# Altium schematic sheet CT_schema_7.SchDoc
size 479 x 328 mm
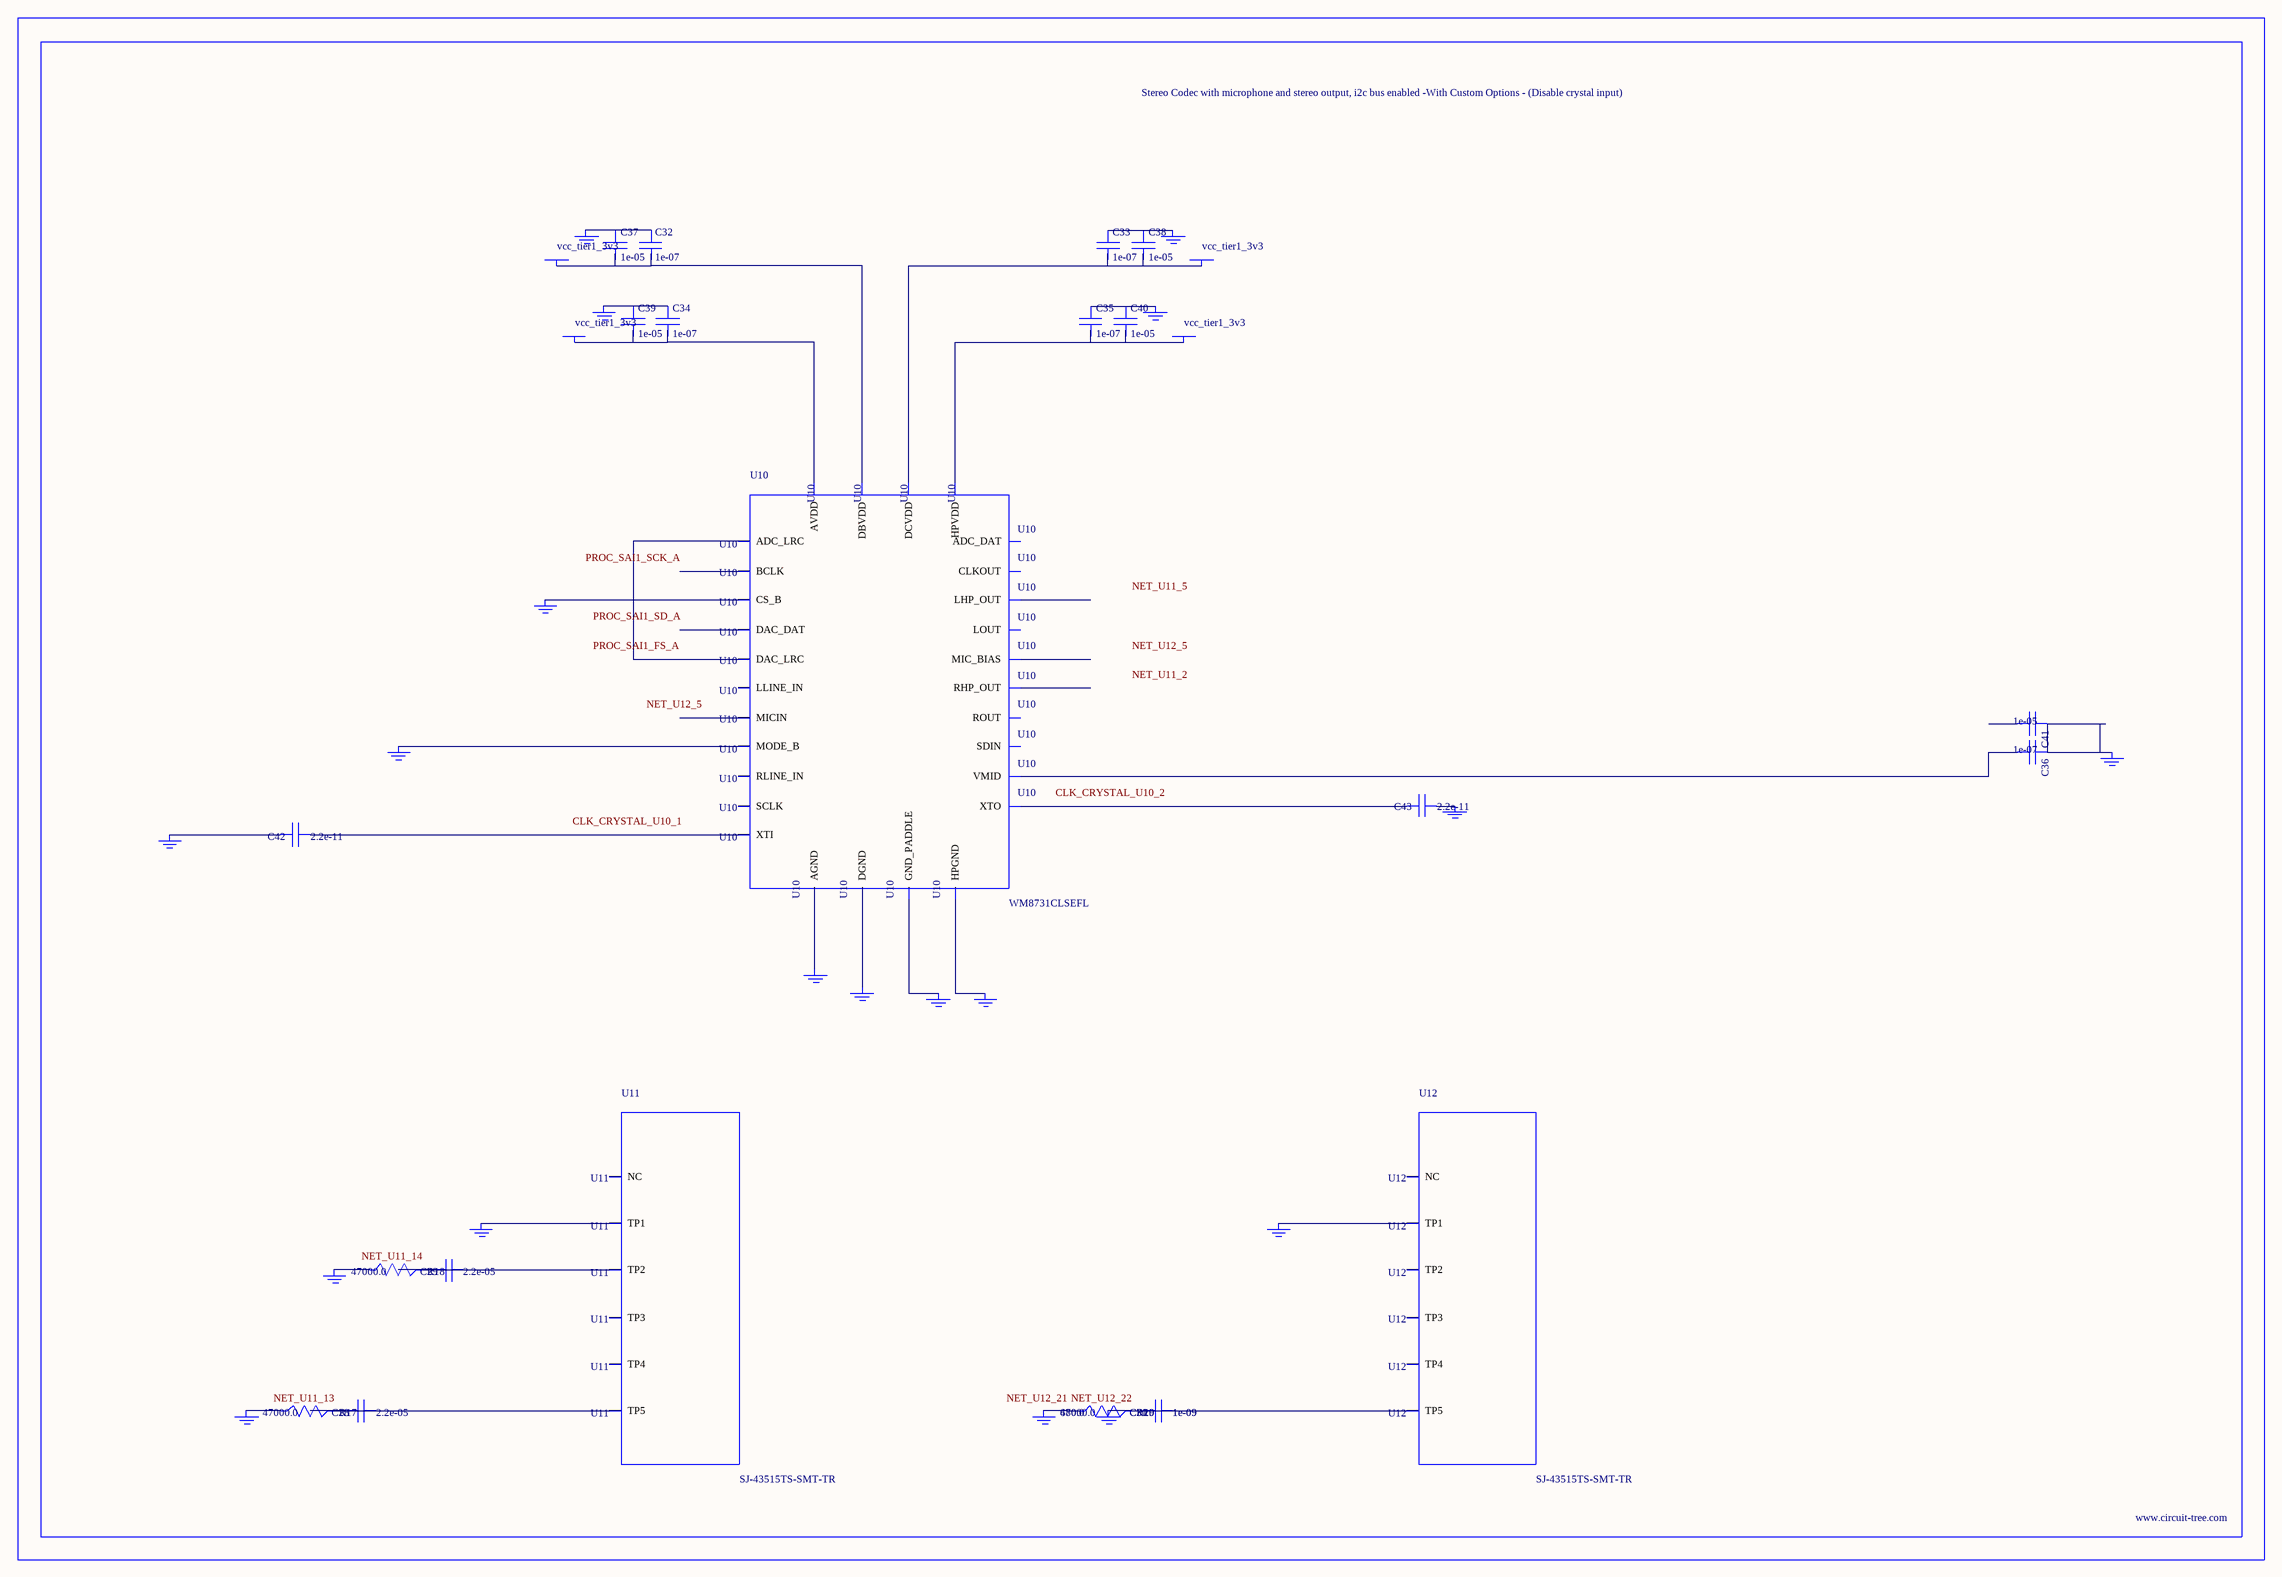
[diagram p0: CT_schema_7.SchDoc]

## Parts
BORDER6  (no value)
C28  2.2e-05  [C1210]
C29  2.2e-05  [C1210]
C30  1e-09  [C0402]
C31  1e-09  [C0402]
C32  1e-07  [C0402]
C33  1e-07  [C0402]
C34  1e-07  [C0402]
C35  1e-07  [C0402]
C36  1e-07  [C0402]
C37  1e-05  [C0805]
C38  1e-05  [C0805]
C39  1e-05  [C0805]
C40  1e-05  [C0805]
C41  1e-05  [C0805]
C42  2.2e-11  [C0402]
C43  2.2e-11  [C0402]
GND_INSTANCE_6_0  (no value)
GND_INSTANCE_6_1  (no value)
GND_INSTANCE_6_2  (no value)
GND_INSTANCE_6_3  (no value)
GND_INSTANCE_6_4  (no value)
GND_INSTANCE_6_5  (no value)
GND_INSTANCE_6_6  (no value)
GND_INSTANCE_6_7  (no value)
GND_INSTANCE_6_8  (no value)
GND_INSTANCE_6_9  (no value)
GND_INSTANCE_6_10  (no value)
GND_INSTANCE_6_11  (no value)
GND_INSTANCE_6_12  (no value)
GND_INSTANCE_6_13  (no value)
GND_INSTANCE_6_14  (no value)
GND_INSTANCE_6_15  (no value)
GND_INSTANCE_6_16  (no value)
GND_INSTANCE_6_17  (no value)
GND_INSTANCE_6_18  (no value)
POWER_INSTANCE_6_0  vcc_tier1_3v3
POWER_INSTANCE_6_1  vcc_tier1_3v3
POWER_INSTANCE_6_2  vcc_tier1_3v3
POWER_INSTANCE_6_3  vcc_tier1_3v3
R17  47000.0  [R0603]
R18  47000.0  [R0603]
R19  47000.0  [R0603]
R20  680.0  [R0603]
U10  WM8731CLSEFL  [QFN-28]
U11  SJ-43515TS-SMT-TR  [SJ-43515TS-SMT-TR]
U12  SJ-43515TS-SMT-TR  [SJ-43515TS-SMT-TR]

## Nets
NetC28_1: C28.1 C28.2 R17.2 U11.5(TP5)
NetC29_1: C29.1 C29.2 R18.2 U11.2(TP2)
NetC30_1: C30.1 C30.2 C31.1 C31.2 GND_INSTANCE_6_18.0(GND) R19.2 R20.2 U12.5(TP5)
NetC32_1: C32.1 C37.1 GND_INSTANCE_6_3.0(GND)
NetC32_2: C32.2 C37.2 POWER_INSTANCE_6_1.0(PWR) U10.5(DBVDD)
NetC33_1: C33.1 C38.1 GND_INSTANCE_6_2.0(GND)
NetC33_2: C33.2 C38.2 POWER_INSTANCE_6_0.0(PWR) U10.3(DCVDD)
NetC34_1: C34.1 C39.1 GND_INSTANCE_6_6.0(GND)
NetC34_2: C34.2 C39.2 POWER_INSTANCE_6_3.0(PWR) U10.18(AVDD)
NetC35_1: C35.1 C40.1 GND_INSTANCE_6_4.0(GND)
NetC35_2: C35.2 C40.2 POWER_INSTANCE_6_2.0(PWR) U10.12(HPVDD)
NetC36_1: C36.1 C41.1 GND_INSTANCE_6_7.0(GND)
NetC36_2: C36.2 U10.20(VMID)
NetC42_1: C42.1 U10.1(XTI)
NetC42_2: C42.2 GND_INSTANCE_6_0.0(GND)
NetC43_1: C43.1 GND_INSTANCE_6_1.0(GND)
NetC43_2: C43.2 U10.2(XTO)
NetGND_INSTANCE_6_5_0: GND_INSTANCE_6_5.0(GND) U10.15(HPGND)
NetGND_INSTANCE_6_8_0: GND_INSTANCE_6_8.0(GND) U10.25(MODE_B)
NetGND_INSTANCE_6_9_0: GND_INSTANCE_6_9.0(GND) U10.26(CS_B)
NetGND_INSTANCE_6_10_0: GND_INSTANCE_6_10.0(GND) U10.29(GND_PADDLE)
NetGND_INSTANCE_6_11_0: GND_INSTANCE_6_11.0(GND) U10.4(DGND)
NetGND_INSTANCE_6_12_0: GND_INSTANCE_6_12.0(GND) U10.19(AGND)
NetGND_INSTANCE_6_13_0: GND_INSTANCE_6_13.0(GND) U11.1(TP1)
NetGND_INSTANCE_6_14_0: GND_INSTANCE_6_14.0(GND) R18.1
NetGND_INSTANCE_6_15_0: GND_INSTANCE_6_15.0(GND) R17.1
NetGND_INSTANCE_6_16_0: GND_INSTANCE_6_16.0(GND) U12.1(TP1)
NetGND_INSTANCE_6_17_0: GND_INSTANCE_6_17.0(GND) R19.1 R20.1
NetU10_9: U10.9(DAC_LRC) U10.11(ADC_LRC)

Not connected (* = marked no-connect by the designer): C41 2; U10 6(CLKOUT) 7(BCLK) 8(DAC_DAT) 10(ADC_DAT) 13(LHP_OUT) 14(RHP_OUT) 16(LOUT) 17(ROUT) 21(MIC_BIAS) 22(MICIN) 23(RLINE_IN) 24(LLINE_IN) 27(SDIN) 28(SCLK); U11 3(TP3) 4(TP4) 6(NC); U12 2(TP2) 3(TP3) 4(TP4) 6(NC)

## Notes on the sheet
- Labels drawn without touching a wire or pin: CLK_CRYSTAL_U10_1, CLK_CRYSTAL_U10_2, NET_U11_2, NET_U11_5, NET_U11_13, NET_U11_14, NET_U12_5, NET_U12_21, NET_U12_22, PROC_SAI1_FS_A, PROC_SAI1_SCK_A, PROC_SAI1_SD_A

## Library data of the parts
BORDER6 = BORDER_PAGE6
C28 C29 = C1210C224K5RACTU
C30 C31 = C0402C102K3RAC
C32-C36 = C0402C104K3RACTU
C37-C41 = C0805C106K8RACTU
C42 C43 = C0402C220K3RAC
GND_INSTANCE_6_0-GND_INSTANCE_6_18 = GND
POWER_INSTANCE_6_0-POWER_INSTANCE_6_3 = PWR
R17-R19 = RC0603JR-0747KL
R20 = RC0603JR-07680RL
